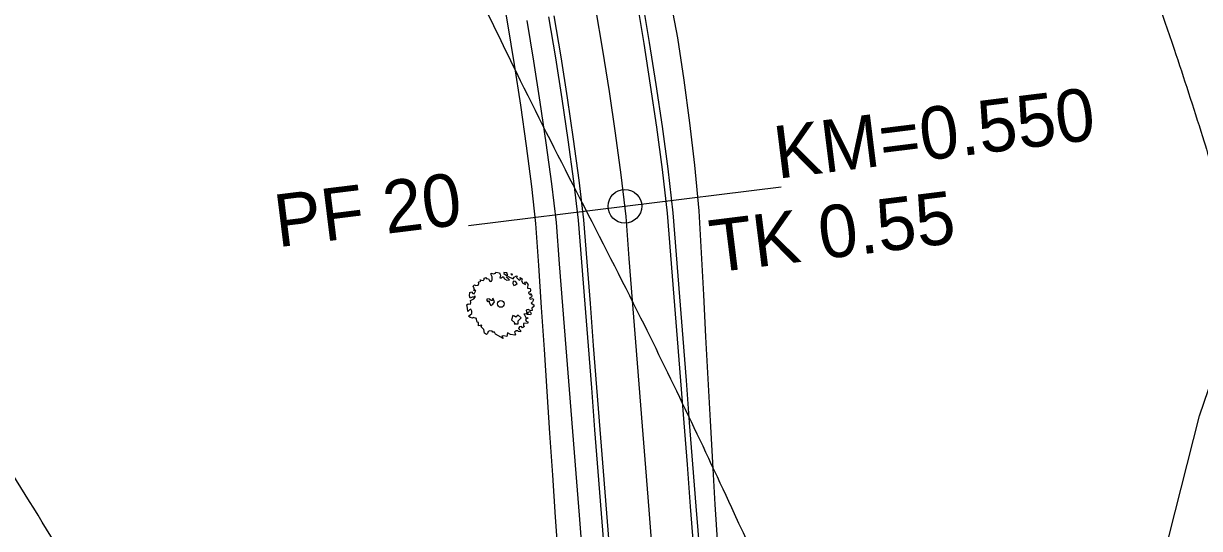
# Model space of a CAD drawing. Extents: x -477701 to -476785, y -1116511 to -1115314.
# Drawn here: x -477417.3 to -477361.3, y -1115753.1 to -1115729 of the extents above; entities that cross this region are included whole.
import ezdxf

# ---------------------------------------------------------------- set-up
doc = ezdxf.new("R2010")
doc.units = 0
for name, color, linetype in [('1', 7, 'Continuous'), ('hrana_P', 7, 'Continuous'), ('hrana_R', 7, 'Continuous'), ('IP_RBK', 7, 'Continuous'), ('POLYGONY_SITUACE_PF', 7, 'Continuous'), ('POLYGONY_SITUACE_PF_POPISY', 7, 'Continuous'), ('POLYGONY_SITUACE_PO', 7, 'Continuous'), ('SVK_STAT', 7, 'Continuous'), ('Vrstevnice_vedlejsi', 7, 'Continuous')]:
    doc.layers.add(name, color=color, linetype=linetype)

msp = doc.modelspace()

# ---------------------------------------------------------------- linework, layer by layer
at = {"layer": 'hrana_P'}
for points in [[(-477394.245, -1115729.048), (-477394.582, -1115727.119)], [(-477386.165, -1115729.721), (-477386.539, -1115727.719)], [(-477393.929, -1115730.979), (-477394.245, -1115729.048)], [(-477385.865, -1115731.735), (-477386.165, -1115729.721)], [(-477393.634, -1115732.915), (-477393.929, -1115730.979)], [(-477385.596, -1115733.753), (-477385.865, -1115731.735)], [(-477393.36, -1115734.853), (-477393.634, -1115732.915)], [(-477385.35, -1115735.774), (-477385.596, -1115733.753)], [(-477393.107, -1115736.794), (-477393.36, -1115734.853)], [(-477385.148, -1115737.949), (-477385.35, -1115735.774)], [(-477392.911, -1115738.558), (-477393.107, -1115736.794)], [(-477385.039, -1115739.946), (-477385.148, -1115737.949)], [(-477392.777, -1115740.554), (-477392.911, -1115738.558)], [(-477384.93, -1115741.944), (-477385.039, -1115739.946)], [(-477392.642, -1115742.55), (-477392.777, -1115740.554)], [(-477384.821, -1115743.941), (-477384.93, -1115741.944)], [(-477392.508, -1115744.545), (-477392.642, -1115742.55)], [(-477384.712, -1115745.939), (-477384.821, -1115743.941)], [(-477392.374, -1115746.541), (-477392.508, -1115744.545)], [(-477384.602, -1115747.937), (-477384.712, -1115745.939)], [(-477392.24, -1115748.537), (-477392.374, -1115746.541)], [(-477384.493, -1115749.934), (-477384.602, -1115747.937)], [(-477392.106, -1115750.532), (-477392.24, -1115748.537)], [(-477384.384, -1115751.932), (-477384.493, -1115749.934)], [(-477391.972, -1115752.528), (-477392.106, -1115750.532)], [(-477383.991, -1115757.919), (-477384.384, -1115751.932)], [(-477391.557, -1115758.514), (-477391.972, -1115752.528)]]:
    msp.add_lwpolyline(points, dxfattribs=at)
at = {"layer": 'hrana_R'}
for p, q in [((-477387.853, -1115727.946), (-477387.52, -1115729.94)), ((-477387.52, -1115729.94), (-477387.206, -1115731.938)), ((-477387.206, -1115731.938), (-477386.912, -1115733.939)), ((-477386.912, -1115733.939), (-477386.639, -1115735.943)), ((-477386.639, -1115735.943), (-477386.397, -1115738.047)), ((-477386.397, -1115738.047), (-477386.24, -1115740.041)), ((-477386.24, -1115740.041), (-477386.084, -1115742.034)), ((-477386.084, -1115742.034), (-477385.927, -1115744.028)), ((-477385.927, -1115744.028), (-477385.77, -1115746.022)), ((-477385.77, -1115746.022), (-477385.614, -1115748.016)), ((-477385.614, -1115748.016), (-477385.457, -1115750.01)), ((-477385.457, -1115750.01), (-477385.301, -1115752.004)), ((-477385.301, -1115752.004), (-477384.831, -1115757.985))]:
    msp.add_line(p, q, dxfattribs=at)
for points in [[(-477390.071, -1115728.328), (-477389.741, -1115730.3)], [(-477387.767, -1115729.98), (-477388.1, -1115727.988)], [(-477390.373, -1115758.421), (-477390.843, -1115752.439), (-477390.999, -1115750.445), (-477391.156, -1115748.451), (-477391.313, -1115746.458), (-477391.469, -1115744.464), (-477391.783, -1115740.476), (-477391.937, -1115738.501), (-477392.15, -1115736.663), (-477392.416, -1115734.72), (-477392.702, -1115732.773), (-477393.007, -1115730.83), (-477393.331, -1115728.89)], [(-477391.962, -1115730.661), (-477392.288, -1115728.71)], [(-477391.715, -1115730.621), (-477392.042, -1115728.668)], [(-477387.453, -1115731.976), (-477387.767, -1115729.98)], [(-477391.655, -1115732.614), (-477391.962, -1115730.661)], [(-477391.408, -1115732.577), (-477391.715, -1115730.621)], [(-477389.741, -1115730.3), (-477389.431, -1115732.276)], [(-477389.431, -1115732.276), (-477389.14, -1115734.255)], [(-477387.16, -1115733.974), (-477387.453, -1115731.976)], [(-477391.368, -1115734.571), (-477391.655, -1115732.614)], [(-477391.12, -1115734.536), (-477391.408, -1115732.577)], [(-477386.887, -1115735.976), (-477387.16, -1115733.974)], [(-477391.1, -1115736.53), (-477391.368, -1115734.571)], [(-477390.852, -1115736.497), (-477391.12, -1115734.536)], [(-477389.14, -1115734.255), (-477388.869, -1115736.237)], [(-477388.869, -1115736.237), (-477388.64, -1115738.223)], [(-477386.646, -1115738.066), (-477386.887, -1115735.976)], [(-477390.883, -1115738.399), (-477391.1, -1115736.53)], [(-477390.634, -1115738.38), (-477390.852, -1115736.497)], [(-477390.727, -1115740.393), (-477390.883, -1115738.399)], [(-477390.477, -1115740.373), (-477390.634, -1115738.38)], [(-477388.64, -1115738.223), (-477388.483, -1115740.217)], [(-477386.49, -1115740.06), (-477386.646, -1115738.066)], [(-477386.333, -1115742.054), (-477386.49, -1115740.06)], [(-477390.57, -1115742.387), (-477390.727, -1115740.393)], [(-477390.321, -1115742.367), (-477390.477, -1115740.373)], [(-477388.483, -1115740.217), (-477388.327, -1115742.211)], [(-477390.413, -1115744.381), (-477390.57, -1115742.387)], [(-477390.164, -1115744.361), (-477390.321, -1115742.367)], [(-477388.327, -1115742.211), (-477388.17, -1115744.205)], [(-477386.176, -1115744.048), (-477386.333, -1115742.054)], [(-477386.02, -1115746.042), (-477386.176, -1115744.048)], [(-477390.257, -1115746.375), (-477390.413, -1115744.381)], [(-477390.007, -1115746.355), (-477390.164, -1115744.361)], [(-477388.17, -1115744.205), (-477388.014, -1115746.198)], [(-477388.014, -1115746.198), (-477387.857, -1115748.192)], [(-477385.863, -1115748.036), (-477386.02, -1115746.042)], [(-477390.1, -1115748.368), (-477390.257, -1115746.375)], [(-477389.851, -1115748.349), (-477390.007, -1115746.355)], [(-477389.943, -1115750.362), (-477390.1, -1115748.368)], [(-477389.694, -1115750.343), (-477389.851, -1115748.349)], [(-477387.857, -1115748.192), (-477387.7, -1115750.186)], [(-477385.706, -1115750.029), (-477385.863, -1115748.036)], [(-477387.7, -1115750.186), (-477387.544, -1115752.18)], [(-477385.55, -1115752.023), (-477385.706, -1115750.029)], [(-477389.787, -1115752.356), (-477389.943, -1115750.362)], [(-477389.537, -1115752.337), (-477389.694, -1115750.343)], [(-477389.317, -1115758.338), (-477389.787, -1115752.356)], [(-477389.068, -1115758.318), (-477389.537, -1115752.337)], [(-477387.544, -1115752.18), (-477387.074, -1115758.162)], [(-477385.08, -1115758.005), (-477385.55, -1115752.023)]]:
    msp.add_lwpolyline(points, dxfattribs=at)
at = {"layer": 'IP_RBK'}
for points in [[(-477393.665, -1115741.119), (-477393.57, -1115741.192), (-477393.592, -1115741.274), (-477393.534, -1115741.387), (-477393.399, -1115741.449), (-477393.442, -1115741.339), (-477393.391, -1115741.324), (-477393.277, -1115741.448), (-477393.299, -1115741.441), (-477393.308, -1115741.63), (-477393.191, -1115741.643), (-477393.166, -1115741.726), (-477393.181, -1115741.802), (-477393.248, -1115741.818), (-477393.266, -1115741.863), (-477393.169, -1115741.961), (-477393.156, -1115741.882), (-477393.096, -1115741.973), (-477393.12, -1115742.059), (-477393.218, -1115742.092), (-477393.188, -1115742.152), (-477393.064, -1115742.125), (-477393.029, -1115742.185), (-477393.067, -1115742.272), (-477393.142, -1115742.345), (-477393.006, -1115742.427), (-477393.008, -1115742.506), (-477393.1, -1115742.589), (-477393.09, -1115742.688), (-477393.159, -1115742.704), (-477393.282, -1115742.645), (-477393.374, -1115742.676), (-477393.358, -1115742.778), (-477393.271, -1115742.832), (-477393.278, -1115742.778), (-477393.234, -1115742.754), (-477393.177, -1115742.743), (-477393.13, -1115742.841), (-477393.172, -1115742.898), (-477393.316, -1115742.878), (-477393.366, -1115742.846), (-477393.489, -1115742.863), (-477393.476, -1115742.868), (-477393.386, -1115743.028), (-477393.281, -1115743.042), (-477393.402, -1115743.12), (-477393.378, -1115743.198), (-477393.292, -1115743.234), (-477393.294, -1115743.296), (-477393.503, -1115743.307), (-477393.508, -1115743.409), (-477393.45, -1115743.459), (-477393.554, -1115743.519), (-477393.598, -1115743.454), (-477393.686, -1115743.475), (-477393.738, -1115743.554), (-477393.647, -1115743.649), (-477393.646, -1115743.705), (-477393.732, -1115743.692), (-477393.777, -1115743.662), (-477393.855, -1115743.666), (-477393.924, -1115743.719), (-477393.875, -1115743.821), (-477393.917, -1115743.86), (-477394.116, -1115743.838), (-477394.263, -1115743.76), (-477394.301, -1115743.934), (-477394.434, -1115743.898), (-477394.528, -1115743.909), (-477394.468, -1115744.017), (-477394.839, -1115743.825), (-477394.883, -1115743.721), (-477394.966, -1115743.717), (-477394.984, -1115743.669), (-477395.1, -1115743.667), (-477395.188, -1115743.684), (-477395.206, -1115743.785), (-477395.262, -1115743.829), (-477395.362, -1115743.778), (-477395.382, -1115743.596), (-477395.516, -1115743.467), (-477395.477, -1115743.395), (-477395.634, -1115743.424), (-477395.645, -1115743.267), (-477395.701, -1115743.249), (-477395.742, -1115743.105), (-477395.741, -1115743.071), (-477395.889, -1115743.031), (-477395.932, -1115743.056), (-477396.034, -1115743.018), (-477396.114, -1115742.967), (-477395.963, -1115742.832), (-477395.959, -1115742.725), (-477396.003, -1115742.634), (-477396.072, -1115742.656), (-477396.141, -1115742.738), (-477396.161, -1115742.585), (-477396.199, -1115742.427), (-477396.137, -1115742.371), (-477396.015, -1115742.397), (-477396.003, -1115742.318), (-477396.024, -1115742.221), (-477395.859, -1115742.135), (-477395.796, -1115742.062), (-477395.807, -1115742.002), (-477395.87, -1115742.051), (-477395.943, -1115742.051), (-477396.03, -1115742.105), (-477396.064, -1115741.993), (-477396.055, -1115741.831), (-477395.978, -1115741.8), (-477395.912, -1115741.878), (-477395.842, -1115741.903), (-477395.776, -1115741.768), (-477395.77, -1115741.745), (-477395.869, -1115741.744), (-477395.832, -1115741.668), (-477395.86, -1115741.621), (-477395.888, -1115741.538), (-477395.83, -1115741.472), (-477395.764, -1115741.501), (-477395.65, -1115741.49), (-477395.621, -1115741.401), (-477395.633, -1115741.346), (-477395.531, -1115741.29), (-477395.557, -1115741.23), (-477395.426, -1115741.257), (-477395.367, -1115741.224), (-477395.37, -1115741.157), (-477395.283, -1115741.128), (-477395.275, -1115741.173), (-477395.222, -1115741.169), (-477395.166, -1115741.186), (-477395.144, -1115741.21), (-477395.135, -1115741.253), (-477395.107, -1115741.291), (-477395.073, -1115741.318), (-477395.019, -1115741.303), (-477394.996, -1115741.239), (-477394.995, -1115741.097), (-477395.042, -1115740.988), (-477395.037, -1115740.921), (-477394.92, -1115740.941), (-477394.837, -1115740.912), (-477394.817, -1115740.862), (-477394.642, -1115740.901), (-477394.628, -1115740.945), (-477394.588, -1115741.006), (-477394.623, -1115741.133), (-477394.56, -1115741.138), (-477394.46, -1115741.081), (-477394.397, -1115741.183), (-477394.291, -1115741.253), (-477394.161, -1115741.226), (-477394.324, -1115741.083), (-477394.237, -1115741.075), (-477393.995, -1115741.188), (-477393.943, -1115741.102), (-477393.835, -1115741.038), (-477393.806, -1115741.051), (-477393.836, -1115741.117), (-477393.703, -1115741.248), (-477393.642, -1115741.22)], [(-477394.434, -1115740.932), (-477394.32, -1115741.004), (-477394.246, -1115741.013), (-477394.294, -1115740.915), (-477394.273, -1115740.899), (-477394.432, -1115740.877)], [(-477394.097, -1115740.953), (-477394.048, -1115741.004), (-477394.018, -1115740.98), (-477394.033, -1115740.957)], [(-477393.997, -1115741.304), (-477394.014, -1115741.404), (-477393.964, -1115741.501), (-477393.876, -1115741.468), (-477393.805, -1115741.401), (-477393.878, -1115741.313)], [(-477395.135, -1115742.228), (-477395.135, -1115742.319), (-477395.053, -1115742.448), (-477394.956, -1115742.386), (-477394.874, -1115742.274), (-477394.952, -1115742.108), (-477394.972, -1115742.22), (-477395.038, -1115742.209), (-477395.099, -1115742.164), (-477395.126, -1115742.145), (-477395.246, -1115742.159), (-477395.239, -1115742.219), (-477395.207, -1115742.268), (-477395.16, -1115742.249)], [(-477394.001, -1115742.923), (-477394.074, -1115743.133), (-477393.907, -1115743.287), (-477393.938, -1115743.322), (-477393.753, -1115743.326), (-477393.749, -1115743.185), (-477393.615, -1115743.043), (-477393.757, -1115742.909), (-477393.86, -1115743.017), (-477393.926, -1115742.955)]]:
    msp.add_lwpolyline(points, close=True, dxfattribs=at)
msp.add_circle((-477394.582, -1115742.381), 0.158, dxfattribs=at)
at = {"layer": 'POLYGONY_SITUACE_PF'}
msp.add_lwpolyline([(-477396.122, -1115738.652), (-477388.679, -1115737.731), (-477381.236, -1115736.809)], dxfattribs=at)
at = {"layer": 'POLYGONY_SITUACE_PO'}
msp.add_circle((-477388.679, -1115737.731), 0.8, dxfattribs=at)
at = {"layer": 'SVK_STAT'}
msp.add_lwpolyline([(-477374.289, -1115790.361), (-477368.016, -1115774.06), (-477361.35, -1115747.71), (-477353.906, -1115725.94), (-477352.679, -1115715.642), (-477354.67, -1115710.782), (-477360.527, -1115707.826), (-477373.875, -1115703.455), (-477387.183, -1115700.691), (-477392.642, -1115700.158), (-477393.082, -1115698.805), (-477390.172, -1115692.166), (-477386.479, -1115677.608), (-477384.394, -1115660.299), (-477383.557, -1115651.168), (-477382.283, -1115647.465), (-477379.37, -1115642.174), (-477377.272, -1115640.926), (-477373.055, -1115640.159), (-477356.644, -1115643.459), (-477334.727, -1115648.433)], dxfattribs=at)
at = {"layer": 'Vrstevnice_vedlejsi'}
for points in [[(-477535.93, -1115532.82), (-477534.231, -1115534.826), (-477529.55, -1115540.603), (-477524.775, -1115546.882), (-477521.239, -1115551.827), (-477518.943, -1115555.44), (-477517.886, -1115557.72), (-477517.005, -1115559.768), (-477516.301, -1115561.585), (-477515.773, -1115563.17), (-477514.249, -1115568.143), (-477511.731, -1115576.504), (-477508.218, -1115588.252), (-477503.131, -1115599.263), (-477496.47, -1115609.538), (-477488.235, -1115619.076), (-477482.234, -1115626.134), (-477478.468, -1115630.712), (-477476.937, -1115632.811), (-477475.949, -1115634.309), (-477475.506, -1115635.207), (-477475.606, -1115635.504), (-477475.009, -1115636.168), (-477473.714, -1115637.2), (-477471.722, -1115638.6), (-477467.091, -1115642.447), (-477459.82, -1115648.74), (-477449.91, -1115657.48), (-477441.655, -1115664.837), (-477435.056, -1115670.813), (-477430.112, -1115675.407), (-477426.12, -1115679.408), (-477423.08, -1115682.818), (-477420.993, -1115685.636), (-477418.264, -1115689.357), (-477414.894, -1115693.981), (-477410.881, -1115699.507), (-477407.419, -1115704.78), (-477404.507, -1115709.801), (-477402.145, -1115714.569), (-477400.568, -1115717.748), (-477399.774, -1115719.338), (-477399.764, -1115719.338), (-477399.751, -1115719.361), (-477399.735, -1115719.406), (-477399.716, -1115719.475), (-477399.696, -1115719.545), (-477399.675, -1115719.618), (-477399.654, -1115719.693), (-477399.629, -1115719.768), (-477399.599, -1115719.845), (-477399.566, -1115719.922), (-477399.526, -1115720.024), (-477399.48, -1115720.149), (-477399.428, -1115720.299), (-477397.485, -1115724.164), (-477393.652, -1115731.746), (-477387.928, -1115743.044), (-477383.476, -1115752.353), (-477380.296, -1115759.674), (-477378.386, -1115765.008), (-477376.582, -1115770.037), (-477374.882, -1115774.763), (-477373.286, -1115779.185), (-477372.202, -1115782.353), (-477371.628, -1115784.267), (-477371.566, -1115784.927), (-477371.519, -1115785.601), (-477371.488, -1115786.291), (-477371.473, -1115786.997), (-477371.503, -1115787.551), (-477371.579, -1115787.953), (-477371.701, -1115788.205), (-477371.905, -1115788.793), (-477372.19, -1115789.717), (-477372.558, -1115790.978), (-477373.011, -1115792.65), (-477373.549, -1115794.733), (-477374.173, -1115797.226), (-477374.607, -1115798.989), (-477374.851, -1115800.019), (-477374.905, -1115800.319), (-477374.939, -1115800.599), (-477374.955, -1115800.858)], [(-477287.632, -1116051.539), (-477286.32, -1116047.536), (-477285.638, -1116044.105), (-477285.587, -1116041.246), (-477286.167, -1116038.959), (-477287.659, -1116036.397), (-477290.063, -1116033.561), (-477293.379, -1116030.449), (-477295.283, -1116025.963), (-477295.775, -1116020.104), (-477294.854, -1116012.871), (-477293.825, -1116007.495), (-477292.688, -1116003.976), (-477291.442, -1116002.315), (-477290.445, -1115998.859), (-477289.699, -1115993.611), (-477289.202, -1115986.569), (-477288.676, -1115980.878), (-477288.121, -1115976.537), (-477287.537, -1115973.548), (-477287.201, -1115971.521), (-477287.115, -1115970.456), (-477287.276, -1115970.354), (-477288.335, -1115969.099), (-477290.29, -1115966.689), (-477293.142, -1115963.125), (-477296.708, -1115959.125), (-477300.986, -1115954.688), (-477305.978, -1115949.815), (-477309.475, -1115946.392), (-477311.478, -1115944.42), (-477311.987, -1115943.899), (-477313.16, -1115942.38), (-477314.997, -1115939.862), (-477317.498, -1115936.346), (-477320.422, -1115932.577), (-477323.768, -1115928.554), (-477327.536, -1115924.277), (-477331.317, -1115918.9), (-477335.113, -1115912.423), (-477338.922, -1115904.846), (-477342.49, -1115897.876), (-477345.815, -1115891.512), (-477348.9, -1115885.756), (-477351.846, -1115880.306), (-477354.656, -1115875.16), (-477357.328, -1115870.321), (-477360.247, -1115865.399), (-477363.413, -1115860.395), (-477366.825, -1115855.308), (-477369.7, -1115850.782), (-477372.037, -1115846.815), (-477373.837, -1115843.407), (-477376.016, -1115839.798), (-477378.575, -1115835.985), (-477381.514, -1115831.971), (-477383.772, -1115828.71), (-477385.347, -1115826.203), (-477386.24, -1115824.45), (-477387.833, -1115820.914), (-477390.124, -1115815.596), (-477393.114, -1115808.495), (-477395.102, -1115803.67), (-477396.086, -1115801.12), (-477396.068, -1115800.846), (-477396.049, -1115800.554), (-477396.029, -1115800.243), (-477396.007, -1115799.914), (-477396.014, -1115799.611), (-477396.048, -1115799.335), (-477396.111, -1115799.086), (-477396.578, -1115797.601), (-477397.449, -1115794.879), (-477398.725, -1115790.921), (-477400.833, -1115785.286), (-477403.776, -1115777.975), (-477407.552, -1115768.988), (-477412.65, -1115759.156), (-477419.071, -1115748.481), (-477426.814, -1115736.962), (-477432.395, -1115728.678), (-477435.814, -1115723.629), (-477437.071, -1115721.814), (-477437.943, -1115720.536), (-477438.43, -1115719.794), (-477438.532, -1115719.589), (-477438.752, -1115719.242), (-477439.089, -1115718.756), (-477439.545, -1115718.129), (-477443.189, -1115713.546), (-477450.023, -1115705.007), (-477460.046, -1115692.512), (-477467.831, -1115683.216), (-477473.377, -1115677.119), (-477476.685, -1115674.221), (-477481.13, -1115671.048), (-477486.712, -1115667.599)], [(-477374.578, -1115696.895), (-477373.99, -1115698.54), (-477373.592, -1115699.926), (-477373.385, -1115701.054), (-477373.369, -1115701.922), (-477373.348, -1115702.539), (-477373.32, -1115702.904), (-477373.287, -1115703.017), (-477373.273, -1115703.149), (-477373.277, -1115703.299), (-477373.299, -1115703.467), (-477373.235, -1115703.727), (-477373.085, -1115704.078), (-477372.848, -1115704.521), (-477371.973, -1115706.486), (-477370.46, -1115709.975), (-477368.309, -1115714.988), (-477366.274, -1115720.038), (-477364.355, -1115725.125), (-477362.552, -1115730.251), (-477361.204, -1115734.416), (-477360.312, -1115737.623), (-477359.875, -1115739.87), (-477359.32, -1115742.334), (-477358.649, -1115745.015), (-477357.861, -1115747.913), (-477357.364, -1115750.107), (-477357.16, -1115751.597), (-477357.247, -1115752.382), (-477357.352, -1115753.597), (-477357.474, -1115755.241), (-477357.614, -1115757.315), (-477357.665, -1115758.846), (-477357.629, -1115759.835), (-477357.504, -1115760.282), (-477357.238, -1115760.772), (-477356.83, -1115761.304), (-477356.28, -1115761.88), (-477355.619, -1115762.282), (-477354.846, -1115762.511), (-477353.961, -1115762.567), (-477353.363, -1115762.954), (-477353.05, -1115763.672), (-477353.023, -1115764.72), (-477353.062, -1115766.083), (-477353.167, -1115767.761), (-477353.338, -1115769.754), (-477353.616, -1115772.773), (-477354.003, -1115776.82), (-477354.364, -1115780.527)], [(-477337.266, -1115946.887), (-477348.633, -1115933.773), (-477356.25, -1115924.996), (-477360.116, -1115920.556), (-477360.231, -1115920.451), (-477360.332, -1115920.343), (-477360.417, -1115920.231), (-477360.487, -1115920.116), (-477362.086, -1115917.208), (-477365.214, -1115911.509), (-477369.87, -1115903.018), (-477373.961, -1115895.74), (-477377.487, -1115889.676), (-477380.447, -1115884.825), (-477383.162, -1115880.486), (-477385.631, -1115876.66), (-477387.854, -1115873.346), (-477390.44, -1115869.048), (-477393.387, -1115863.766), (-477396.696, -1115857.501), (-477399.966, -1115852.076), (-477403.196, -1115847.491), (-477406.387, -1115843.745), (-477409.557, -1115839.142), (-477412.706, -1115833.68), (-477415.833, -1115827.36), (-477419.365, -1115820.809), (-477423.302, -1115814.027), (-477427.644, -1115807.013), (-477431.429, -1115800.502), (-477434.657, -1115794.492), (-477437.328, -1115788.984), (-477440.163, -1115783.757), (-477443.16, -1115778.81), (-477446.319, -1115774.144), (-477449.256, -1115769.981), (-477451.971, -1115766.319), (-477454.463, -1115763.16), (-477457.329, -1115759.698), (-477460.57, -1115755.933), (-477464.185, -1115751.866), (-477467.95, -1115747.267), (-477471.866, -1115742.136), (-477475.933, -1115736.472), (-477480.254, -1115731.495), (-477484.827, -1115727.205), (-477489.655, -1115723.603), (-477494.56, -1115720.054), (-477499.544, -1115716.559), (-477504.606, -1115713.117), (-477509.129, -1115709.621), (-477513.112, -1115706.071), (-477513.981, -1115705.193), (-477514.797, -1115704.267), (-477515.631, -1115703.342), (-477516.556, -1115702.467), (-477521.43, -1115700.546), (-477527.734, -1115700.309), (-477529.666, -1115700.63), (-477531.592, -1115701.045), (-477533.522, -1115701.453), (-477535.469, -1115701.756), (-477542.487, -1115702.155), (-477548.79, -1115701.506), (-477550.21, -1115701.152), (-477551.595, -1115700.671), (-477552.975, -1115700.184), (-477554.378, -1115699.809), (-477559.514, -1115699.703), (-477564.199, -1115701.187), (-477568.432, -1115704.261), (-477572.401, -1115707.717), (-477576.106, -1115711.556), (-477579.547, -1115715.778), (-477582.875, -1115719.448), (-477586.091, -1115722.567), (-477589.196, -1115725.133), (-477592.121, -1115728.755), (-477594.867, -1115733.431), (-477597.433, -1115739.162), (-477599.711, -1115744.095), (-477601.7, -1115748.229), (-477603.4, -1115751.564), (-477604.536, -1115754.357), (-477605.107, -1115756.608), (-477605.113, -1115758.317), (-477606.183, -1115762.278), (-477607.852, -1115767.203)]]:
    msp.add_spline(points, degree=3, dxfattribs=at)

# ---------------------------------------------------------------- texts
at = {"layer": '1'}
msp.add_text('TK 0.55', height=2.5, rotation=7.059, dxfattribs=at).set_placement((-477384.475, -1115740.896))
at = {"layer": 'POLYGONY_SITUACE_PF_POPISY'}
for s, p in [('KM=0.550', (-477381.421, -1115736.425)), ('PF 20', (-477405.187, -1115739.685))]:
    msp.add_text(s, height=2.5, rotation=7.0565, dxfattribs=at).set_placement(p)

doc.saveas('drawing.dxf')
